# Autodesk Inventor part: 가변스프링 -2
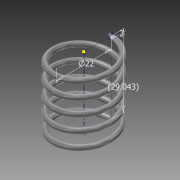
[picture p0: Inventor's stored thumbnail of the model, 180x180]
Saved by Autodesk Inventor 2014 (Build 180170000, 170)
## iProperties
Created: 2016-01
Part Number: 가변스프링 -2
Material: 스테인레스 스틸
Document SubType Name: Modeling
Designer: Administrator
Density: 8.08 g/cm^3
Appearance: 반연마
Mass: 8.62004 g
Surface Area: 21.6891 cm^2
Volume: 1.06684 cm^3
Author: Administrator
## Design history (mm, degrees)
sketch "스케치1"
  geometry: L1 (0, -29.043)-(11, -29.043); L2 (11, -29.043)-(11, 0); L3 (11, 0)-(0, 0); L4 (0, 0)-(0, -29.043); C1 r 1 at (11, 0); 1 further point
  constraints: 8 end point, 2 coincident, 2 parallel, 1 centre point, 1 horizontal, 1 perpendicular
  dimensions: "d0" = 2 diameter of C1; "d1" = 22 diameter of L2 L4; "d2" = 29.04259 distance of L1.end L2.end (derived)
feature "코일1" pitch "d3" = 10; turns "d5" = 5; dims "d4" = 29.04259 (= d2), "d6" = 0, angle "d7" = 90 deg, angle "d8" = 90 deg, "d9" = 0, "d10" = 0
sketch "스케치4"
  geometry: L1 (0, 10)-(0, 12) reference; 1 further point
  constraints: 1 vertical alignment
extrude "돌출3" cut sketch "스케치4" distance "d16" = 10; taper "d17" = 0 deg
node "작업 평면2"
sketch "스케치5"
  geometry: L1 (12, 0)-(10, 0) reference; 1 further point
  constraints: 1 horizontal alignment
extrude "돌출4" cut sketch "스케치5" distance "d19" = 10; taper "d20" = 0 deg
node "솔리드1"
node "절단 모서리 투영3"
node "절단 모서리 투영4"
other parameters: "d18" = 0
